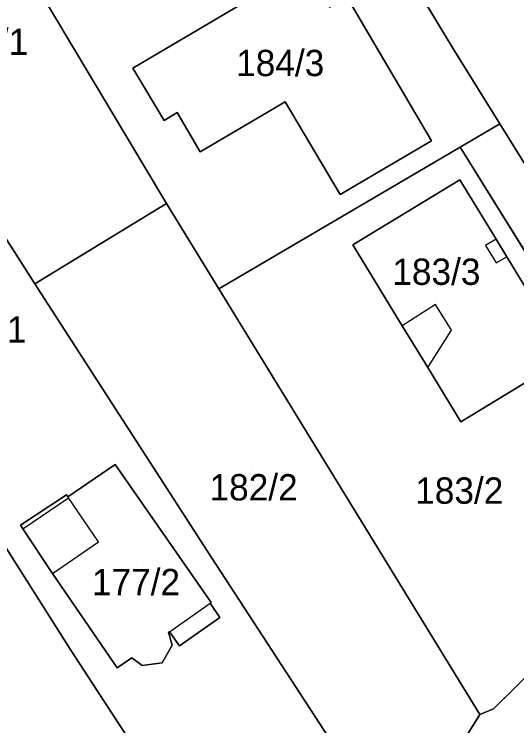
# Model space of a CAD drawing. Extents: x -263943 to -261149, y -1236934 to -1230686.
# Drawn here: x -262396.2 to -262358.1, y -1235796.1 to -1235742.1 of the extents above; entities that cross this region are included whole.
import ezdxf

# ---------------------------------------------------------------- set-up
doc = ezdxf.new("R2010")
doc.units = 0
for name, color, linetype in [('body_kn', 7, 'Continuous'), ('kladpar_druhypozemkov', 7, 'Continuous'), ('kladpar_hranice', 7, 'Continuous'), ('kladpar_parcelnecisla', 7, 'Continuous'), ('kladpar_plochy', 7, 'Continuous'), ('zappar_hrandruhpozemk', 7, 'Continuous')]:
    doc.layers.add(name, color=color, linetype=linetype)

msp = doc.modelspace()

# ---------------------------------------------------------------- linework, layer by layer
at = {"layer": 'body_kn'}
for p, q in [((-262362.93, -1235744.63), (-262362.93, -1235744.63)), ((-262362.93, -1235744.63), (-262362.93, -1235744.63)), ((-262387.22, -1235746.15), (-262387.22, -1235746.15)), ((-262375.67, -1235748.72), (-262375.67, -1235748.72)), ((-262383.86, -1235749.51), (-262383.86, -1235749.51)), ((-262384.85, -1235750.14), (-262384.85, -1235750.14)), ((-262359.36, -1235750.38), (-262359.36, -1235750.38)), ((-262359.36, -1235750.38), (-262359.36, -1235750.38)), ((-262364.55, -1235751.68), (-262364.55, -1235751.68)), ((-262362.38, -1235752.15), (-262362.38, -1235752.15)), ((-262362.38, -1235752.15), (-262362.38, -1235752.15)), ((-262382.12, -1235752.52), (-262382.12, -1235752.52)), ((-262362.39, -1235754.63), (-262362.39, -1235754.63)), ((-262371.49, -1235755.76), (-262371.49, -1235755.76)), ((-262384.68, -1235756.43), (-262384.68, -1235756.43)), ((-262359.65, -1235759.14), (-262359.65, -1235759.14)), ((-262359.65, -1235759.14), (-262359.65, -1235759.14)), ((-262370.53, -1235759.57), (-262370.53, -1235759.57)), ((-262370.53, -1235759.57), (-262370.53, -1235759.57)), ((-262360.45, -1235759.62), (-262360.45, -1235759.62)), ((-262359.64, -1235760.95), (-262359.64, -1235760.95)), ((-262358.84, -1235760.48), (-262358.84, -1235760.48)), ((-262394.66, -1235762.54), (-262394.66, -1235762.54)), ((-262380.7, -1235762.92), (-262380.7, -1235762.92)), ((-262364.24, -1235764.11), (-262364.24, -1235764.11)), ((-262366.78, -1235765.73), (-262366.78, -1235765.73)), ((-262363.03, -1235766.07), (-262363.03, -1235766.07)), ((-262364.84, -1235768.91), (-262364.84, -1235768.91)), ((-262364.84, -1235768.91), (-262364.84, -1235768.91)), ((-262362.33, -1235773.03), (-262362.33, -1235773.03)), ((-262388.57, -1235776.26), (-262388.57, -1235776.26)), ((-262392.27, -1235778.58), (-262392.27, -1235778.58)), ((-262392.16, -1235778.72), (-262392.16, -1235778.72)), ((-262392.1, -1235778.81), (-262392.1, -1235778.81)), ((-262392.1, -1235778.81), (-262392.1, -1235778.81)), ((-262395.74, -1235780.89), (-262395.74, -1235780.89)), ((-262395.58, -1235781.15), (-262395.58, -1235781.15)), ((-262395.58, -1235781.15), (-262395.58, -1235781.15)), ((-262389.82, -1235782.15), (-262389.82, -1235782.15)), ((-262381.57, -1235782.84), (-262381.57, -1235782.84)), ((-262381.57, -1235782.84), (-262381.57, -1235782.84)), ((-262393.33, -1235784.56), (-262393.33, -1235784.56)), ((-262393.33, -1235784.56), (-262393.33, -1235784.56)), ((-262381.35, -1235786.81), (-262381.35, -1235786.81)), ((-262381.27, -1235786.76), (-262381.27, -1235786.76)), ((-262380.61, -1235787.9), (-262380.61, -1235787.9)), ((-262384.51, -1235789.02), (-262384.51, -1235789.02)), ((-262384.45, -1235788.98), (-262384.45, -1235788.98)), ((-262384.45, -1235788.98), (-262384.45, -1235788.98)), ((-262384.24, -1235790), (-262384.24, -1235790)), ((-262383.69, -1235790.05), (-262383.69, -1235790.05)), ((-262383.69, -1235790.05), (-262383.69, -1235790.05)), ((-262391.97, -1235790.31), (-262391.97, -1235790.31)), ((-262387.31, -1235790.96), (-262387.31, -1235790.96)), ((-262388.41, -1235791.72), (-262388.41, -1235791.72)), ((-262386.52, -1235791.55), (-262386.52, -1235791.55)), ((-262385, -1235791.33), (-262385, -1235791.33)), ((-262359.85, -1235794.84), (-262359.85, -1235794.84)), ((-262360.87, -1235795.26), (-262360.87, -1235795.26))]:
    msp.add_line(p, q, dxfattribs=at)
at = {"layer": 'kladpar_druhypozemkov'}
for p, q in [((-262375.46, -1235744.82), (-262375.46, -1235744.82)), ((-262363.24, -1235760.57), (-262363.24, -1235760.57)), ((-262378.12, -1235776.75), (-262378.12, -1235776.75)), ((-262362.03, -1235777.38), (-262362.03, -1235777.38)), ((-262386.96, -1235783.7), (-262386.96, -1235783.7))]:
    msp.add_line(p, q, dxfattribs=at)
at = {"layer": 'kladpar_hranice'}
for points in [[(-262379.1, -1235824.92), (-262397.29, -1235796.67), (-262418.29, -1235763.17), (-262430.23, -1235743.91), (-262431.98, -1235741.09), (-262442.29, -1235724.3), (-262438.67, -1235722.03), (-262438.04, -1235723.06), (-262436.85, -1235722.38), (-262437.54, -1235721.32), (-262436.26, -1235720.52), (-262438.35, -1235717.28), (-262437.77, -1235716.92), (-262415.1, -1235753.76), (-262391.97, -1235790.31), (-262374.2, -1235817.63), (-262379.1, -1235824.92)], [(-262362.93, -1235744.63), (-262373.9, -1235726.44), (-262363.41, -1235719.06), (-262344.96, -1235748.67), (-262329.4, -1235773.2), (-262341.51, -1235779.15)], [(-262380.7, -1235762.92), (-262384.68, -1235756.43), (-262394.71, -1235739.59), (-262384.56, -1235731.37), (-262386.6, -1235727.98), (-262376.96, -1235721.7), (-262373.9, -1235726.44), (-262362.93, -1235744.63), (-262359.36, -1235750.38)], [(-262404.61, -1235746.98), (-262413.19, -1235733.27), (-262411.65, -1235732.35), (-262402.62, -1235726.91), (-262394.71, -1235739.59), (-262384.68, -1235756.43), (-262394.66, -1235762.54), (-262404.61, -1235746.98)], [(-262371.49, -1235755.76), (-262364.55, -1235751.68), (-262370.99, -1235740.72), (-262372.29, -1235741.53), (-262374.09, -1235738.39), (-262387.22, -1235746.15), (-262384.85, -1235750.14), (-262383.86, -1235749.51), (-262382.12, -1235752.52), (-262375.67, -1235748.72), (-262371.49, -1235755.76)], [(-262374.09, -1235738.39), (-262372.29, -1235741.53), (-262370.99, -1235740.72), (-262364.55, -1235751.68), (-262371.49, -1235755.76), (-262375.67, -1235748.72), (-262382.12, -1235752.52), (-262383.86, -1235749.51), (-262384.85, -1235750.14), (-262387.22, -1235746.15), (-262374.09, -1235738.39)], [(-262341.51, -1235779.15), (-262359.36, -1235750.38), (-262362.93, -1235744.63)], [(-262374.2, -1235817.63), (-262391.97, -1235790.31), (-262415.1, -1235753.76), (-262404.61, -1235746.98), (-262394.66, -1235762.54), (-262381.57, -1235782.84), (-262367.03, -1235805.18)], [(-262359.36, -1235750.38), (-262362.38, -1235752.15), (-262380.7, -1235762.92)], [(-262359.36, -1235750.38), (-262341.51, -1235779.15), (-262344.33, -1235781.22), (-262362.38, -1235752.15), (-262359.36, -1235750.38)], [(-262362.38, -1235752.15), (-262344.33, -1235781.22), (-262350.98, -1235786.1), (-262359.85, -1235794.84), (-262360.87, -1235795.26), (-262380.7, -1235762.92), (-262362.38, -1235752.15)], [(-262370.53, -1235759.57), (-262362.39, -1235754.63), (-262359.65, -1235759.14), (-262358.84, -1235760.48), (-262354.21, -1235768.09), (-262362.33, -1235773.03), (-262364.84, -1235768.91), (-262366.78, -1235765.73), (-262370.53, -1235759.57)], [(-262362.39, -1235754.63), (-262370.53, -1235759.57), (-262366.78, -1235765.73), (-262364.84, -1235768.91), (-262362.33, -1235773.03), (-262354.21, -1235768.09), (-262358.84, -1235760.48), (-262359.65, -1235759.14), (-262362.39, -1235754.63)], [(-262381.57, -1235782.84), (-262394.66, -1235762.54), (-262384.68, -1235756.43), (-262380.7, -1235762.92), (-262360.87, -1235795.26), (-262367.03, -1235805.18), (-262381.57, -1235782.84)], [(-262405.39, -1235839.39), (-262385.61, -1235832.55), (-262379.1, -1235824.92), (-262374.2, -1235817.63), (-262367.03, -1235805.18), (-262360.87, -1235795.26), (-262359.85, -1235794.84), (-262350.98, -1235786.1), (-262344.33, -1235781.22), (-262341.51, -1235779.15), (-262329.4, -1235773.2), (-262321.79, -1235770.57), (-262313.91, -1235767.93)], [(-262395.58, -1235781.15), (-262393.33, -1235784.56), (-262388.41, -1235791.72), (-262387.31, -1235790.96), (-262386.52, -1235791.55), (-262385, -1235791.33), (-262384.24, -1235790), (-262384.51, -1235789.02), (-262384.45, -1235788.98), (-262383.69, -1235790.05), (-262380.61, -1235787.9), (-262381.35, -1235786.81), (-262381.27, -1235786.76), (-262388.57, -1235776.26), (-262392.16, -1235778.72), (-262392.27, -1235778.58), (-262395.74, -1235780.89), (-262395.58, -1235781.15)], [(-262383.69, -1235790.05), (-262384.45, -1235788.98), (-262384.51, -1235789.02), (-262384.24, -1235790), (-262385, -1235791.33), (-262386.52, -1235791.55), (-262387.31, -1235790.96), (-262388.41, -1235791.72), (-262393.33, -1235784.56), (-262395.58, -1235781.15), (-262395.74, -1235780.89), (-262392.27, -1235778.58), (-262392.16, -1235778.72), (-262388.57, -1235776.26), (-262381.27, -1235786.76), (-262381.35, -1235786.81), (-262380.61, -1235787.9), (-262383.69, -1235790.05)]]:
    msp.add_lwpolyline(points, dxfattribs=at)
at = {"layer": 'kladpar_plochy'}
for p, q in [((-262362.93, -1235744.63), (-262373.9, -1235726.44)), ((-262373.9, -1235726.44), (-262362.93, -1235744.63)), ((-262374.09, -1235738.39), (-262387.22, -1235746.15)), ((-262384.68, -1235756.43), (-262394.71, -1235739.59)), ((-262364.55, -1235751.68), (-262370.99, -1235740.72)), ((-262359.36, -1235750.38), (-262362.93, -1235744.63)), ((-262362.93, -1235744.63), (-262359.36, -1235750.38)), ((-262387.22, -1235746.15), (-262384.85, -1235750.14)), ((-262404.61, -1235746.98), (-262394.66, -1235762.54)), ((-262382.12, -1235752.52), (-262375.67, -1235748.72)), ((-262375.67, -1235748.72), (-262371.49, -1235755.76)), ((-262384.85, -1235750.14), (-262383.86, -1235749.51)), ((-262383.86, -1235749.51), (-262382.12, -1235752.52)), ((-262359.36, -1235750.38), (-262362.38, -1235752.15)), ((-262341.51, -1235779.15), (-262359.36, -1235750.38)), ((-262371.49, -1235755.76), (-262364.55, -1235751.68)), ((-262362.38, -1235752.15), (-262380.7, -1235762.92)), ((-262380.7, -1235762.92), (-262362.38, -1235752.15)), ((-262362.38, -1235752.15), (-262344.33, -1235781.22)), ((-262391.97, -1235790.31), (-262415.1, -1235753.76)), ((-262362.39, -1235754.63), (-262370.53, -1235759.57)), ((-262359.65, -1235759.14), (-262362.39, -1235754.63)), ((-262380.7, -1235762.92), (-262384.68, -1235756.43)), ((-262358.84, -1235760.48), (-262359.65, -1235759.14)), ((-262370.53, -1235759.57), (-262366.78, -1235765.73)), ((-262354.21, -1235768.09), (-262358.84, -1235760.48)), ((-262394.66, -1235762.54), (-262381.57, -1235782.84)), ((-262360.87, -1235795.26), (-262380.7, -1235762.92)), ((-262366.78, -1235765.73), (-262364.84, -1235768.91)), ((-262362.33, -1235773.03), (-262354.21, -1235768.09)), ((-262364.84, -1235768.91), (-262362.33, -1235773.03)), ((-262388.57, -1235776.26), (-262392.16, -1235778.72)), ((-262381.27, -1235786.76), (-262388.57, -1235776.26)), ((-262392.27, -1235778.58), (-262395.74, -1235780.89)), ((-262392.16, -1235778.72), (-262392.27, -1235778.58)), ((-262395.74, -1235780.89), (-262395.58, -1235781.15)), ((-262395.58, -1235781.15), (-262393.33, -1235784.56)), ((-262381.57, -1235782.84), (-262367.03, -1235805.18)), ((-262393.33, -1235784.56), (-262388.41, -1235791.72)), ((-262350.98, -1235786.1), (-262359.85, -1235794.84)), ((-262381.35, -1235786.81), (-262381.27, -1235786.76)), ((-262380.61, -1235787.9), (-262381.35, -1235786.81)), ((-262383.69, -1235790.05), (-262380.61, -1235787.9)), ((-262384.51, -1235789.02), (-262384.45, -1235788.98)), ((-262384.24, -1235790), (-262384.51, -1235789.02)), ((-262384.45, -1235788.98), (-262383.69, -1235790.05)), ((-262385, -1235791.33), (-262384.24, -1235790)), ((-262374.2, -1235817.63), (-262391.97, -1235790.31)), ((-262388.41, -1235791.72), (-262387.31, -1235790.96)), ((-262387.31, -1235790.96), (-262386.52, -1235791.55)), ((-262386.52, -1235791.55), (-262385, -1235791.33)), ((-262359.85, -1235794.84), (-262360.87, -1235795.26))]:
    msp.add_line(p, q, dxfattribs=at)
for points in [[(-262379.1, -1235824.92), (-262397.29, -1235796.67), (-262418.29, -1235763.17), (-262430.23, -1235743.91), (-262431.98, -1235741.09), (-262442.29, -1235724.3), (-262438.67, -1235722.03), (-262438.04, -1235723.06), (-262436.85, -1235722.38), (-262437.54, -1235721.32), (-262436.26, -1235720.52), (-262438.35, -1235717.28), (-262437.77, -1235716.92), (-262415.1, -1235753.76), (-262391.97, -1235790.31), (-262374.2, -1235817.63)], [(-262404.61, -1235746.98), (-262413.19, -1235733.27), (-262411.65, -1235732.35), (-262402.62, -1235726.91), (-262394.71, -1235739.59), (-262384.68, -1235756.43), (-262394.66, -1235762.54)], [(-262374.09, -1235738.39), (-262372.29, -1235741.53), (-262370.99, -1235740.72), (-262364.55, -1235751.68), (-262371.49, -1235755.76), (-262375.67, -1235748.72), (-262382.12, -1235752.52), (-262383.86, -1235749.51), (-262384.85, -1235750.14), (-262387.22, -1235746.15)], [(-262359.36, -1235750.38), (-262341.51, -1235779.15), (-262344.33, -1235781.22), (-262362.38, -1235752.15)], [(-262370.53, -1235759.57), (-262362.39, -1235754.63), (-262359.65, -1235759.14), (-262358.84, -1235760.48), (-262354.21, -1235768.09), (-262362.33, -1235773.03), (-262364.84, -1235768.91), (-262366.78, -1235765.73)], [(-262381.57, -1235782.84), (-262394.66, -1235762.54), (-262384.68, -1235756.43), (-262380.7, -1235762.92), (-262360.87, -1235795.26), (-262367.03, -1235805.18)], [(-262383.69, -1235790.05), (-262384.45, -1235788.98), (-262384.51, -1235789.02), (-262384.24, -1235790), (-262385, -1235791.33), (-262386.52, -1235791.55), (-262387.31, -1235790.96), (-262388.41, -1235791.72), (-262393.33, -1235784.56), (-262395.58, -1235781.15), (-262395.74, -1235780.89), (-262392.27, -1235778.58), (-262392.16, -1235778.72), (-262388.57, -1235776.26), (-262381.27, -1235786.76), (-262381.35, -1235786.81), (-262380.61, -1235787.9)]]:
    msp.add_lwpolyline(points, close=True, dxfattribs=at)
msp.add_lwpolyline([(-262405.39, -1235839.39), (-262385.61, -1235832.55), (-262379.1, -1235824.92), (-262374.2, -1235817.63), (-262367.03, -1235805.18), (-262360.87, -1235795.26), (-262359.85, -1235794.84), (-262350.98, -1235786.1), (-262344.33, -1235781.22), (-262341.51, -1235779.15), (-262329.4, -1235773.2), (-262321.79, -1235770.57), (-262313.91, -1235767.93)], dxfattribs=at)
at = {"layer": 'zappar_hrandruhpozemk'}
for p, q in [((-262359.65, -1235759.14), (-262360.45, -1235759.62)), ((-262360.45, -1235759.62), (-262359.64, -1235760.95)), ((-262359.64, -1235760.95), (-262358.84, -1235760.48)), ((-262364.24, -1235764.11), (-262366.78, -1235765.73)), ((-262363.03, -1235766.07), (-262364.24, -1235764.11)), ((-262364.84, -1235768.91), (-262363.03, -1235766.07)), ((-262395.58, -1235781.15), (-262392.1, -1235778.81)), ((-262392.1, -1235778.81), (-262392.16, -1235778.72)), ((-262389.82, -1235782.15), (-262392.1, -1235778.81)), ((-262393.33, -1235784.56), (-262389.82, -1235782.15)), ((-262384.45, -1235788.98), (-262381.35, -1235786.81))]:
    msp.add_line(p, q, dxfattribs=at)

# ---------------------------------------------------------------- texts
at = {"layer": 'kladpar_parcelnecisla'}
for s, p in [('182/1', (-262401.858, -1235745.15)), ('184/3', (-262379.383, -1235746.76)), ('183/3', (-262367.526, -1235762.62)), ('177/1', (-262401.996, -1235767)), ('182/2', (-262381.404, -1235779)), ('183/2', (-262365.79, -1235779.25)), ('177/2', (-262390.332, -1235786.2))]:
    msp.add_text(s, height=2, dxfattribs=at).set_placement(p)

doc.saveas('drawing.dxf')
